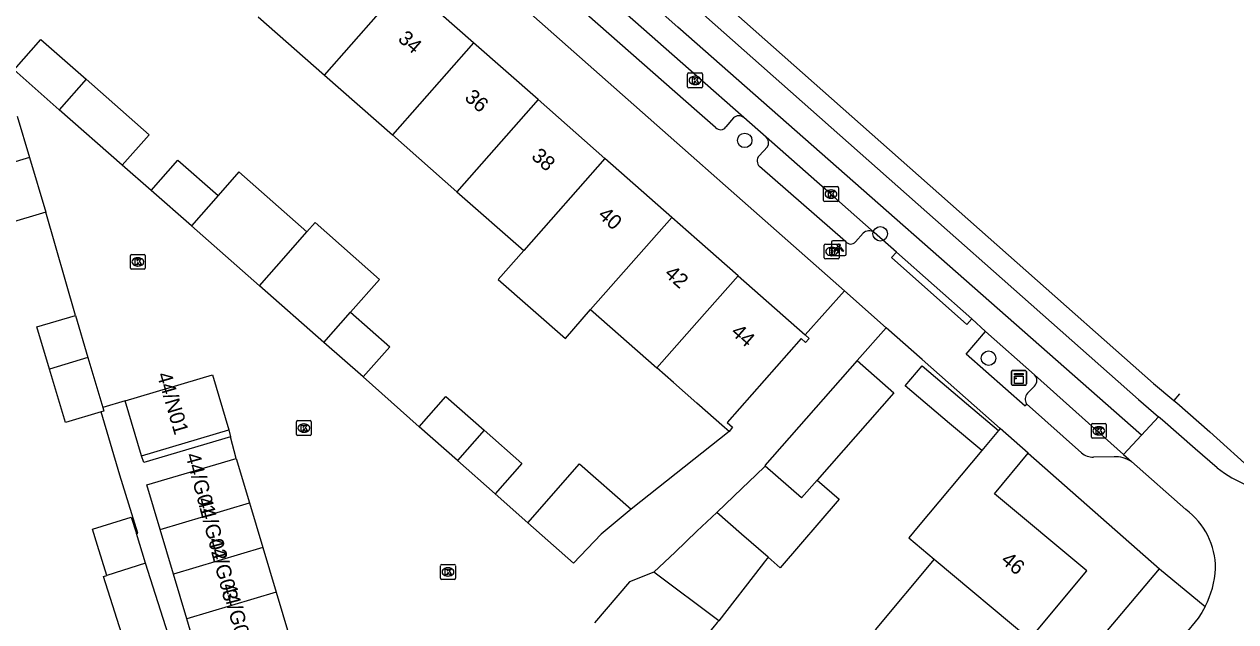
# Model space of a CAD drawing. Extents: x 162532 to 163264, y 381233 to 382042.
# Drawn here: x 162954.6 to 163036.3, y 381826.4 to 381866.7 of the extents above; entities that cross this region are included whole.
import ezdxf

# ---------------------------------------------------------------- set-up
doc = ezdxf.new("R2010")
doc.units = 0
for name, color, linetype in [('IMGEO_Boom', 7, 'Continuous'), ('IMGEO_Brandkraan', 7, 'Continuous'), ('IMGEO_Kast', 7, 'Continuous'), ('IMGEO_Kolk', 7, 'Continuous'), ('IMGEO_Lichtpunt', 7, 'Continuous'), ('IMGEO_Muur', 7, 'Continuous'), ('IMGEO_Pand', 7, 'Continuous'), ('IMGEO_Pand_nummerreeks', 7, 'Continuous'), ('IMGEO_Parkeervlak_open', 7, 'Continuous'), ('IMGEO_Rijbaan_lokaal_gesloten', 7, 'Continuous'), ('IMGEO_Rijbaan_lokaal_open', 7, 'Continuous'), ('IMGEO_Voetpad_open', 7, 'Continuous')]:
    doc.layers.add(name, color=color, linetype=linetype)

msp = doc.modelspace()

# ---------------------------------------------------------------- linework, layer by layer
at = {"layer": 'IMGEO_Boom'}
for centre in [(163003.224, 381858.903), (163012.36, 381852.6), (163019.663, 381844.21)]:
    msp.add_circle(centre, 0.489, dxfattribs=at)
at = {"layer": 'IMGEO_Brandkraan'}
for p, q in [((163008.59, 381850.977), (163008.59, 381851.829)), ((163008.665, 381851.903), (163009.517, 381851.903)), ((163009.078, 381851.683), (163009.103, 381851.683)), ((163009.591, 381851.829), (163009.591, 381850.977)), ((163009.517, 381850.903), (163008.665, 381850.903)), ((163009.101, 381851.123), (163009.076, 381851.123))]:
    msp.add_line(p, q, dxfattribs=at)
for points in [[(163008.59, 381850.977), (163008.59, 381851.829)], [(163008.665, 381851.903), (163009.517, 381851.903)], [(163008.938, 381851.603), (163008.938, 381851.203), (163009.151, 381851.203)], [(163009.169, 381851.603), (163008.938, 381851.603)], [(163009.117, 381851.522), (163009.063, 381851.522), (163009.063, 381851.446)], [(163009.063, 381851.446), (163009.116, 381851.446)], [(163009.591, 381851.829), (163009.591, 381850.977)], [(163009.517, 381850.903), (163008.665, 381850.903)], [(163009.125, 381851.37), (163009.063, 381851.37), (163009.063, 381851.289)], [(163009.063, 381851.289), (163009.125, 381851.289)]]:
    msp.add_lwpolyline(points, dxfattribs=at)
for centre, radius, start, end in [((163008.667, 381851.827), 0.0765, 91.55205, 178.44795), ((163008.667, 381851.827), 0.0765, 91.55205, 178.44795), ((163009.118, 381851.484), 0.0379, 267.82845, 90.93552), ((163009.173, 381851.458), 0.145, 59.4692, 91.53667), ((163009.198, 381851.505), 0.0922, 285.51372, 58.15012), ((163009.515, 381851.827), 0.0765, 1.55205, 88.44795), ((163009.515, 381851.827), 0.0765, 1.55205, 88.44795), ((163008.667, 381850.979), 0.0765, 181.55205, 268.44795), ((163008.667, 381850.979), 0.0765, 181.55205, 268.44795), ((163009.126, 381851.329), 0.0404, 269.87594, 90.50774), ((163009.157, 381851.454), 0.251, 268.66757, 293.53466), ((163009.203, 381851.313), 0.105, 301.31148, 78.98903), ((163009.515, 381850.979), 0.0765, 271.55205, 358.44795), ((163009.515, 381850.979), 0.0765, 271.55205, 358.44795)]:
    msp.add_arc(centre, radius, start, end, dxfattribs=at)
for centre, major_axis, ratio, start_param, end_param in [((163009.077, 381851.403), (-0.387, 0.002), 0.722429, 4.712389, 7.853982), ((163009.102, 381851.403), (-0.39, 0.002), 0.717154, 1.570796, 4.712389)]:
    msp.add_ellipse(centre, major_axis=major_axis, ratio=ratio, start_param=start_param, end_param=end_param, dxfattribs=at)
at = {"layer": 'IMGEO_Kast'}
for p, q in [((163021.212, 381842.46), (163021.212, 381843.301)), ((163021.212, 381843.301), (163021.212, 381842.46)), ((163021.287, 381843.385), (163022.128, 381843.385)), ((163022.128, 381843.385), (163021.287, 381843.385)), ((163022.212, 381843.31), (163022.212, 381842.469)), ((163022.212, 381842.469), (163022.212, 381843.31)), ((163022.137, 381842.385), (163021.296, 381842.385)), ((163021.296, 381842.385), (163022.137, 381842.385))]:
    msp.add_line(p, q, dxfattribs=at)
for points in [[(163021.407, 381843.175), (163022.007, 381843.175), (163022.007, 381843.09), (163021.407, 381843.09), (163021.407, 381843.175)], [(163021.407, 381843), (163022.007, 381843), (163022.007, 381842.511), (163021.407, 381842.511), (163021.407, 381843)]]:
    msp.add_lwpolyline(points, dxfattribs=at)
msp.add_circle((163021.491, 381842.849), 0.0377, dxfattribs=at)
for centre, start, end in [((163021.29, 381843.307), 92.4484, 184.28452), ((163021.29, 381843.307), 92.4484, 184.28452), ((163022.134, 381843.307), 2.4484, 94.28452), ((163022.134, 381843.307), 2.4484, 94.28452), ((163021.29, 381842.463), 182.4484, 274.28452), ((163021.29, 381842.463), 182.4484, 274.28452), ((163022.134, 381842.463), 272.4484, 4.28452), ((163022.134, 381842.463), 272.4484, 4.28452)]:
    msp.add_arc(centre, 0.0779, start, end, dxfattribs=at)
at = {"layer": 'IMGEO_Kolk'}
for p, q in [((162999.376, 381862.523), (162999.376, 381863.375)), ((162999.451, 381863.449), (163000.303, 381863.449)), ((162999.864, 381863.229), (162999.889, 381863.229)), ((163000.377, 381863.375), (163000.377, 381862.523)), ((163000.303, 381862.449), (162999.451, 381862.449)), ((162999.887, 381862.669), (162999.862, 381862.669)), ((163008.542, 381854.856), (163008.542, 381855.708)), ((163008.617, 381855.782), (163009.469, 381855.782)), ((163009.03, 381855.562), (163009.055, 381855.562)), ((163009.543, 381855.708), (163009.543, 381854.856)), ((163009.469, 381854.782), (163008.617, 381854.782)), ((163009.053, 381855.002), (163009.028, 381855.002)), ((162961.809, 381850.279), (162961.809, 381851.131)), ((162961.884, 381851.205), (162962.736, 381851.205)), ((162962.297, 381850.985), (162962.322, 381850.985)), ((162962.81, 381851.131), (162962.81, 381850.279)), ((162962.736, 381850.205), (162961.884, 381850.205)), ((162962.32, 381850.425), (162962.295, 381850.425)), ((162973.004, 381839.07), (162973.004, 381839.922)), ((162973.079, 381839.996), (162973.931, 381839.996)), ((162973.515, 381839.216), (162973.49, 381839.216)), ((162973.492, 381839.776), (162973.517, 381839.776)), ((162974.005, 381839.922), (162974.005, 381839.07)), ((163026.594, 381838.883), (163026.594, 381839.735)), ((163026.669, 381839.809), (163027.521, 381839.809)), ((163027.082, 381839.589), (163027.107, 381839.589)), ((163027.595, 381839.735), (163027.595, 381838.883)), ((162973.931, 381838.996), (162973.079, 381838.996)), ((163027.521, 381838.809), (163026.669, 381838.809)), ((163027.105, 381839.029), (163027.08, 381839.029)), ((162982.717, 381829.362), (162982.717, 381830.214)), ((162982.792, 381830.288), (162983.644, 381830.288)), ((162983.718, 381830.214), (162983.718, 381829.362)), ((162983.228, 381829.508), (162983.203, 381829.508)), ((162983.205, 381830.068), (162983.23, 381830.068)), ((162983.644, 381829.288), (162982.792, 381829.288))]:
    msp.add_line(p, q, dxfattribs=at)
for points in [[(162999.376, 381862.523), (162999.376, 381863.375)], [(162999.451, 381863.449), (163000.303, 381863.449)], [(162999.697, 381863.149), (162999.82, 381863.149), (162999.82, 381862.998), (162999.95, 381863.149), (163000.114, 381863.149), (162999.968, 381862.998), (163000.121, 381862.749), (162999.969, 381862.749), (162999.884, 381862.913), (162999.82, 381862.846), (162999.82, 381862.749), (162999.697, 381862.749), (162999.697, 381863.149)], [(163000.377, 381863.375), (163000.377, 381862.523)], [(163000.303, 381862.449), (162999.451, 381862.449)], [(163008.542, 381854.856), (163008.542, 381855.708)], [(163008.617, 381855.782), (163009.469, 381855.782)], [(163009.543, 381855.708), (163009.543, 381854.856)], [(163009.469, 381854.782), (163008.617, 381854.782)], [(163008.863, 381855.482), (163008.986, 381855.482), (163008.986, 381855.331), (163009.116, 381855.482), (163009.28, 381855.482), (163009.134, 381855.331), (163009.287, 381855.082), (163009.135, 381855.082), (163009.05, 381855.246), (163008.986, 381855.179), (163008.986, 381855.082), (163008.863, 381855.082), (163008.863, 381855.482)], [(162961.809, 381850.279), (162961.809, 381851.131)], [(162961.884, 381851.205), (162962.736, 381851.205)], [(162962.13, 381850.905), (162962.253, 381850.905), (162962.253, 381850.754), (162962.383, 381850.905), (162962.547, 381850.905), (162962.401, 381850.754), (162962.554, 381850.505), (162962.402, 381850.505), (162962.317, 381850.669), (162962.253, 381850.602), (162962.253, 381850.505), (162962.13, 381850.505), (162962.13, 381850.905)], [(162962.81, 381851.131), (162962.81, 381850.279)], [(162962.736, 381850.205), (162961.884, 381850.205)], [(162973.004, 381839.07), (162973.004, 381839.922)], [(162973.079, 381839.996), (162973.931, 381839.996)], [(162973.325, 381839.696), (162973.448, 381839.696), (162973.448, 381839.545), (162973.578, 381839.696), (162973.742, 381839.696), (162973.596, 381839.545), (162973.749, 381839.296), (162973.597, 381839.296), (162973.512, 381839.46), (162973.448, 381839.393), (162973.448, 381839.296), (162973.325, 381839.296), (162973.325, 381839.696)], [(162974.005, 381839.922), (162974.005, 381839.07)], [(163026.594, 381838.883), (163026.594, 381839.735)], [(163026.669, 381839.809), (163027.521, 381839.809)], [(163026.915, 381839.509), (163027.038, 381839.509), (163027.038, 381839.358), (163027.168, 381839.509), (163027.332, 381839.509), (163027.186, 381839.358), (163027.339, 381839.109), (163027.187, 381839.109), (163027.102, 381839.273), (163027.038, 381839.206), (163027.038, 381839.109), (163026.915, 381839.109), (163026.915, 381839.509)], [(163027.595, 381839.735), (163027.595, 381838.883)], [(162973.931, 381838.996), (162973.079, 381838.996)], [(163027.521, 381838.809), (163026.669, 381838.809)], [(162982.717, 381829.362), (162982.717, 381830.214)], [(162982.792, 381830.288), (162983.644, 381830.288)], [(162983.718, 381830.214), (162983.718, 381829.362)], [(162983.038, 381829.988), (162983.161, 381829.988), (162983.161, 381829.837), (162983.291, 381829.988), (162983.455, 381829.988), (162983.309, 381829.837), (162983.462, 381829.588), (162983.31, 381829.588), (162983.225, 381829.752), (162983.161, 381829.685), (162983.161, 381829.588), (162983.038, 381829.588), (162983.038, 381829.988)], [(162983.644, 381829.288), (162982.792, 381829.288)]]:
    msp.add_lwpolyline(points, dxfattribs=at)
for centre, start, end in [((162999.453, 381863.373), 91.55205, 178.44795), ((162999.453, 381863.373), 91.55205, 178.44795), ((163000.301, 381863.373), 1.55205, 88.44795), ((163000.301, 381863.373), 1.55205, 88.44795), ((162999.453, 381862.525), 181.55205, 268.44795), ((162999.453, 381862.525), 181.55205, 268.44795), ((163000.301, 381862.525), 271.55205, 358.44795), ((163000.301, 381862.525), 271.55205, 358.44795), ((163008.619, 381855.706), 91.55205, 178.44795), ((163008.619, 381855.706), 91.55205, 178.44795), ((163009.467, 381855.706), 1.55205, 88.44795), ((163009.467, 381855.706), 1.55205, 88.44795), ((163008.619, 381854.858), 181.55205, 268.44795), ((163008.619, 381854.858), 181.55205, 268.44795), ((163009.467, 381854.858), 271.55205, 358.44795), ((163009.467, 381854.858), 271.55205, 358.44795), ((162961.886, 381851.129), 91.55205, 178.44795), ((162961.886, 381851.129), 91.55205, 178.44795), ((162962.734, 381851.129), 1.55205, 88.44795), ((162962.734, 381851.129), 1.55205, 88.44795), ((162961.886, 381850.281), 181.55205, 268.44795), ((162961.886, 381850.281), 181.55205, 268.44795), ((162962.734, 381850.281), 271.55205, 358.44795), ((162962.734, 381850.281), 271.55205, 358.44795), ((162973.081, 381839.92), 91.55205, 178.44795), ((162973.081, 381839.92), 91.55205, 178.44795), ((162973.929, 381839.92), 1.55205, 88.44795), ((162973.929, 381839.92), 1.55205, 88.44795), ((163026.671, 381839.733), 91.55205, 178.44795), ((163026.671, 381839.733), 91.55205, 178.44795), ((163027.519, 381839.733), 1.55205, 88.44795), ((163027.519, 381839.733), 1.55205, 88.44795), ((162973.081, 381839.072), 181.55205, 268.44795), ((162973.081, 381839.072), 181.55205, 268.44795), ((162973.929, 381839.072), 271.55205, 358.44795), ((162973.929, 381839.072), 271.55205, 358.44795), ((163026.671, 381838.885), 181.55205, 268.44795), ((163026.671, 381838.885), 181.55205, 268.44795), ((163027.519, 381838.885), 271.55205, 358.44795), ((163027.519, 381838.885), 271.55205, 358.44795), ((162982.794, 381830.212), 91.55205, 178.44795), ((162982.794, 381830.212), 91.55205, 178.44795), ((162983.642, 381830.212), 1.55205, 88.44795), ((162983.642, 381830.212), 1.55205, 88.44795), ((162982.794, 381829.364), 181.55205, 268.44795), ((162982.794, 381829.364), 181.55205, 268.44795), ((162983.642, 381829.364), 271.55205, 358.44795), ((162983.642, 381829.364), 271.55205, 358.44795)]:
    msp.add_arc(centre, 0.0765, start, end, dxfattribs=at)
for centre, major_axis, ratio, start_param, end_param in [((162999.863, 381862.949), (-0.387, 0.002), 0.722429, 4.712389, 7.853982), ((162999.888, 381862.949), (-0.39, 0.002), 0.717154, 1.570796, 4.712389), ((163009.029, 381855.282), (-0.387, 0.002), 0.722429, 4.712389, 7.853982), ((163009.054, 381855.282), (-0.39, 0.002), 0.717154, 1.570796, 4.712389), ((162962.296, 381850.705), (-0.387, 0.002), 0.722429, 4.712389, 7.853982), ((162962.321, 381850.705), (-0.39, 0.002), 0.717154, 1.570796, 4.712389), ((162973.491, 381839.496), (-0.387, 0.002), 0.722429, 4.712389, 7.853982), ((162973.516, 381839.496), (-0.39, 0.002), 0.717154, 1.570796, 4.712389), ((163027.081, 381839.309), (-0.387, 0.002), 0.722429, 4.712389, 7.853982), ((163027.106, 381839.309), (-0.39, 0.002), 0.717154, 1.570796, 4.712389), ((162983.204, 381829.788), (-0.387, 0.002), 0.722429, 4.712389, 7.853982), ((162983.229, 381829.788), (-0.39, 0.002), 0.717154, 1.570796, 4.712389)]:
    msp.add_ellipse(centre, major_axis=major_axis, ratio=ratio, start_param=start_param, end_param=end_param, dxfattribs=at)
at = {"layer": 'IMGEO_Lichtpunt'}
for p, q in [((163009.068, 381852.028), (163009.068, 381851.221)), ((163009.068, 381852.028), (163009.068, 381851.221)), ((163009.97, 381852.123), (163009.162, 381852.123)), ((163009.97, 381852.123), (163009.162, 381852.123)), ((163010.064, 381851.221), (163010.064, 381852.028)), ((163010.064, 381851.221), (163010.064, 381852.028)), ((163009.162, 381851.127), (163009.97, 381851.127)), ((163009.162, 381851.127), (163009.97, 381851.127))]:
    msp.add_line(p, q, dxfattribs=at)
for points in [[(163009.442, 381851.692), (163009.481, 381851.664), (163009.293, 381851.402), (163009.255, 381851.429), (163009.442, 381851.692)], [(163009.544, 381851.644), (163009.591, 381851.644), (163009.591, 381851.322), (163009.544, 381851.322), (163009.544, 381851.644)], [(163009.654, 381851.664), (163009.692, 381851.691), (163009.879, 381851.429), (163009.84, 381851.401), (163009.654, 381851.664)]]:
    msp.add_lwpolyline(points, dxfattribs=at)
msp.add_circle((163009.567, 381851.826), 0.0994, dxfattribs=at)
for centre, start, end in [((163009.162, 381852.028), 90, 180), ((163009.162, 381852.028), 90, 180), ((163009.97, 381852.028), 0, 90), ((163009.97, 381852.028), 0, 90), ((163009.162, 381851.221), 180, 270), ((163009.162, 381851.221), 180, 270), ((163009.97, 381851.221), 270, 0), ((163009.97, 381851.221), 270, 360)]:
    msp.add_arc(centre, 0.0946, start, end, dxfattribs=at)
at = {"layer": 'IMGEO_Muur'}
msp.add_lwpolyline([(163002.168, 381839.272), (162995.563, 381834.021)], dxfattribs=at)
at = {"layer": 'IMGEO_Pand'}
for points in [[(162974.886, 381863.312), (162980.362, 381869.524)], [(162984.945, 381865.485), (162980.362, 381869.524)], [(162970.419, 381867.248), (162974.886, 381863.312)], [(162953.965, 381863.657), (162955.774, 381865.71), (162958.82, 381863.026)], [(162984.945, 381865.485), (162979.47, 381859.272)], [(162989.296, 381861.65), (162984.945, 381865.485)], [(162957.011, 381860.973), (162953.965, 381863.657)], [(162958.82, 381863.026), (162957.011, 381860.973)], [(162958.82, 381863.026), (162963.063, 381859.288), (162961.254, 381857.235)], [(162974.886, 381863.312), (162979.47, 381859.272)], [(162989.296, 381861.65), (162983.821, 381855.439)], [(162993.798, 381857.682), (162989.296, 381861.65)], [(162954.166, 381860.543), (162954.996, 381857.752)], [(162961.254, 381857.235), (162957.011, 381860.973)], [(162979.47, 381859.272), (162983.821, 381855.439)], [(162954.996, 381857.752), (162952.367, 381856.971)], [(162954.996, 381857.752), (162956.096, 381854.056)], [(162963.216, 381855.522), (162965.015, 381857.564), (162967.719, 381855.182)], [(162993.798, 381857.682), (162988.324, 381851.471)], [(162998.309, 381853.707), (162993.798, 381857.682)], [(162956.096, 381854.056), (162953.466, 381853.274), (162952.367, 381856.971)], [(162973.712, 381852.737), (162969.126, 381856.778), (162967.719, 381855.182)], [(162965.919, 381853.14), (162963.216, 381855.522)], [(162967.719, 381855.182), (162965.919, 381853.14)], [(162983.821, 381855.439), (162988.324, 381851.471)], [(162970.505, 381849.099), (162965.919, 381853.14)], [(162976.655, 381847.309), (162978.605, 381849.522), (162974.256, 381853.355), (162973.712, 381852.737)], [(162992.834, 381847.497), (162998.309, 381853.707)], [(163002.779, 381849.766), (163000, 381852.216), (162998.309, 381853.707)], [(162970.505, 381849.099), (162972.305, 381851.141), (162973.712, 381852.737)], [(162988.324, 381851.471), (162986.609, 381849.516), (162991.15, 381845.534), (162992.834, 381847.497)], [(162974.854, 381845.267), (162970.505, 381849.099)], [(162997.307, 381843.556), (163000, 381846.613), (163002.779, 381849.766)], [(163002.779, 381849.766), (163007.303, 381845.78)], [(162992.834, 381847.497), (162997.307, 381843.556)], [(162956.353, 381843.476), (162955.506, 381846.323), (162958.098, 381847.094)], [(162958.098, 381847.094), (162958.945, 381844.247)], [(162974.854, 381845.267), (162976.655, 381847.309)], [(162976.655, 381847.309), (162979.293, 381844.985), (162977.493, 381842.942)], [(163007.303, 381845.78), (163007.569, 381845.545), (163007.329, 381845.273), (163007.03, 381845.537), (163002.037, 381839.874), (163002.409, 381839.546), (163002.168, 381839.272)], [(162977.493, 381842.942), (162974.854, 381845.267)], [(162958.945, 381844.247), (162956.353, 381843.476)], [(162958.945, 381844.247), (162959.945, 381840.884)], [(162959.826, 381840.581), (162957.426, 381839.867), (162956.353, 381843.476)], [(163002.168, 381839.272), (163001.86, 381839.544), (163000, 381841.183), (162998.417, 381842.578), (162997.307, 381843.556)], [(163010.813, 381844.047), (163004.569, 381836.966), (163004.609, 381836.93)], [(163010.813, 381844.047), (163013.288, 381841.865), (163008.108, 381835.988)], [(163019.202, 381837.982), (163017.04, 381839.811), (163014.052, 381842.339), (163015.193, 381843.688), (163018.181, 381841.16), (163020.334, 381839.338)], [(162961.462, 381841.336), (162967.333, 381843.083), (162968.436, 381839.372)], [(162959.945, 381840.884), (162960.018, 381840.638), (162959.826, 381840.581)], [(162962.566, 381837.626), (162961.462, 381841.336)], [(162981.28, 381839.575), (162983.082, 381841.62), (162985.654, 381839.354)], [(162962.566, 381837.626), (162968.436, 381839.372)], [(162983.852, 381837.309), (162981.28, 381839.575)], [(162985.654, 381839.354), (162983.852, 381837.309)], [(162985.654, 381839.354), (162988.204, 381837.107), (162986.402, 381835.061)], [(163020.334, 381839.338), (163019.202, 381837.982)], [(163020.45, 381839.477), (163020.334, 381839.338)], [(163022.344, 381837.805), (163020.45, 381839.477)], [(163019.202, 381837.982), (163014.913, 381832.847), (163014.279, 381832.088), (163015.993, 381830.656)], [(163022.448, 381825.264), (163026.287, 381829.86), (163020.055, 381835.066), (163022.344, 381837.805)], [(162963.812, 381832.65), (162962.918, 381835.657), (162968.948, 381837.45)], [(162968.948, 381837.45), (162969.842, 381834.443)], [(162986.402, 381835.061), (162983.852, 381837.309)], [(162988.598, 381833.103), (162992.096, 381837.075), (162995.563, 381834.021)], [(163004.609, 381836.93), (163003.972, 381836.322), (163003.049, 381835.442), (163001.339, 381833.81)], [(163008.108, 381835.988), (163007.045, 381834.783), (163004.609, 381836.93)], [(163008.108, 381835.988), (163009.581, 381834.699), (163005.62, 381830.065), (163004.802, 381830.78)], [(162963.812, 381832.65), (162969.842, 381834.443)], [(162969.842, 381834.443), (162970.737, 381831.437)], [(162960.213, 381829.556), (162959.588, 381831.566), (162959.244, 381832.672), (162961.866, 381833.489), (162962.21, 381832.382)], [(162995.563, 381834.021), (162993.54, 381832.337), (162991.685, 381830.384), (162988.598, 381833.103)], [(163001.339, 381833.81), (163000, 381832.532), (162998.532, 381831.131), (162997.107, 381829.771)], [(163004.802, 381830.78), (163003.018, 381832.341), (163001.339, 381833.81)], [(162962.829, 381830.391), (162962.21, 381832.382)], [(162964.707, 381829.643), (162963.812, 381832.65)], [(162970.737, 381831.437), (162964.707, 381829.643)], [(162970.737, 381831.437), (162971.631, 381828.43)], [(162962.829, 381830.391), (162960.213, 381829.556)], [(162964.294, 381825.56), (162964.364, 381825.582), (162962.829, 381830.391)], [(163004.802, 381830.78), (163004.732, 381830.69), (163004.629, 381830.557), (163004.565, 381830.475), (163004.343, 381830.188), (163001.473, 381826.491)], [(163015.993, 381830.656), (163012.008, 381825.886)], [(163015.993, 381830.656), (163022.448, 381825.264)], [(162964.294, 381825.56), (162961.523, 381824.675), (162959.988, 381829.484), (162960.213, 381829.556)], [(162965.601, 381826.636), (162964.707, 381829.643)], [(162997.107, 381829.771), (162995.45, 381829.117), (162993.09, 381826.366)], [(163001.473, 381826.491), (162997.107, 381829.771)], [(162971.631, 381828.43), (162965.601, 381826.636)], [(162971.631, 381828.43), (162972.525, 381825.423)], [(162966.495, 381823.63), (162965.601, 381826.636)], [(163001.473, 381826.491), (163001.369, 381826.369), (163001.082, 381826.028), (162997.88, 381822.23), (162997.663, 381822.417)]]:
    msp.add_lwpolyline(points, dxfattribs=at)
at = {"layer": 'IMGEO_Parkeervlak_open'}
msp.add_lwpolyline([(163022.767, 381842.333), (163022.282, 381841.85)], dxfattribs=at)
for centre, radius, start, end in [((163022.38, 381842.712), 0.542, 315.56566, 44.58512), ((163022.775, 381841.449), 0.636, 140.85906, 210.8017)]:
    msp.add_arc(centre, radius, start, end, dxfattribs=at)
at = {"layer": 'IMGEO_Rijbaan_lokaal_gesloten'}
for points in [[(162960.555, 381904.688), (162964.495, 381901.237), (163030.789, 381842.506), (163032.151, 381841.367)], [(162959.588, 381903.618), (162963.496, 381900.145), (163029.773, 381841.426), (163031.123, 381840.264)], [(163029.975, 381839.023), (162998.723, 381866.534), (162984.668, 381879.012), (162958.336, 381902.201)], [(163003.157, 381860.44), (163000, 381863.226), (162991.553, 381870.7)], [(163004.675, 381859.124), (163003.157, 381860.44)], [(163011.941, 381852.697), (163009.04, 381855.284), (163004.675, 381859.124)], [(163013.455, 381851.365), (163011.941, 381852.697)], [(163013.455, 381851.365), (163018.527, 381846.856)], [(163019.464, 381846.01), (163018.527, 381846.856)], [(163019.464, 381846.01), (163022.766, 381843.093)], [(163028.767, 381837.716), (163022.766, 381843.093)]]:
    msp.add_lwpolyline(points, dxfattribs=at)
at = {"layer": 'IMGEO_Rijbaan_lokaal_open'}
for points in [[(162963.216, 381855.522), (162961.254, 381857.235)], [(162958.098, 381847.094), (162956.096, 381854.056)], [(163009.953, 381848.745), (163007.303, 381845.78)], [(163012.767, 381846.26), (163009.953, 381848.745)], [(163012.767, 381846.26), (163010.813, 381844.047)], [(162981.28, 381839.575), (162977.493, 381842.942)], [(163032.53, 381841.809), (163032.151, 381841.367)], [(162961.462, 381841.336), (162959.945, 381840.884)], [(163032.151, 381841.367), (163032.351, 381841.2), (163034.587, 381839.245), (163037.615, 381836.491)], [(163031.123, 381840.264), (163029.975, 381839.023)], [(163035.073, 381836.804), (163033.583, 381838.09), (163031.383, 381840.04), (163031.123, 381840.264)], [(162968.436, 381839.372), (162968.56, 381838.907)], [(163002.168, 381839.272), (162995.563, 381834.021)], [(162968.948, 381837.45), (162968.56, 381838.907)], [(163029.975, 381839.023), (163028.767, 381837.716)], [(163028.767, 381837.716), (163029.301, 381837.237)], [(163029.301, 381837.237), (163032.966, 381834.001)], [(162988.598, 381833.103), (162986.402, 381835.061)], [(163034.271, 381827.468), (163034.045, 381827.064), (163033.791, 381826.677), (163031.945, 381824.423)]]:
    msp.add_lwpolyline(points, dxfattribs=at)
for centre, radius, start, end in [((163040.223, 381843.505), 8.452, 232.45589, 248.77135), ((163029.978, 381829.999), 4.994, 0.19027, 53.24997), ((163028.493, 381830.428), 6.493, 332.8749, 356.36006)]:
    msp.add_arc(centre, radius, start, end, dxfattribs=at)
at = {"layer": 'IMGEO_Voetpad_open'}
for points in [[(162969.525, 381884.497), (163000, 381857.535), (163001.931, 381855.827), (163009.953, 381848.745)], [(163001.263, 381859.77), (163000, 381860.883), (162991.105, 381868.722)], [(163002.457, 381860.419), (163001.956, 381859.806)], [(163004.192, 381857.868), (163004.752, 381858.461)], [(163010.025, 381852.084), (163004.231, 381857.137)], [(163011.212, 381852.638), (163010.703, 381852.049)], [(163018.527, 381846.856), (163018.195, 381846.483), (163013.123, 381850.992), (163013.455, 381851.365)], [(163020.45, 381839.477), (163015.189, 381844.122), (163012.767, 381846.26)], [(163022.229, 381841.123), (163022.134, 381840.979), (163018.152, 381844.491), (163019.464, 381846.01)], [(163025.932, 381837.829), (163022.229, 381841.123)], [(162962.21, 381832.382), (162962.309, 381832.413), (162961.097, 381836.308), (162959.826, 381840.581)], [(162968.56, 381838.907), (162962.715, 381837.168), (162962.566, 381837.626)], [(163022.344, 381837.805), (163031.179, 381830.005)], [(163028.124, 381837.564), (163026.742, 381837.537)], [(162997.617, 381790.181), (162997.806, 381790.405), (163031.179, 381830.005)], [(163031.179, 381830.005), (163034.271, 381827.468)]]:
    msp.add_lwpolyline(points, dxfattribs=at)
for centre, radius, start, end in [((163002.819, 381860.041), 0.523, 49.67655, 133.76017), ((163001.595, 381860.067), 0.445, 221.77948, 324.16799), ((163004.286, 381858.743), 0.544, 328.8126, 44.43657), ((163004.58, 381857.522), 0.52, 138.28689, 227.82096), ((163011.612, 381852.228), 0.573, 54.95455, 134.2995), ((163010.379, 381852.35), 0.442, 216.93044, 317.15932), ((163026.723, 381838.753), 1.216, 229.43854, 270.91362), ((163028.181, 381835.488), 2.077, 57.3733, 91.57346)]:
    msp.add_arc(centre, radius, start, end, dxfattribs=at)

# ---------------------------------------------------------------- texts
at = {"layer": 'IMGEO_Pand_nummerreeks'}
for s, rotation, p in [('34', 318.60769, (162979.781, 381865.665)), ('36', 318.60769, (162984.278, 381861.701)), ('38', 318.60769, (162988.777, 381857.735)), ('40', 318.60769, (162993.274, 381853.772)), ('42', 318.60769, (162997.752, 381849.824)), ('44', 318.6084, (163002.236, 381845.873)), ('44/N01', 286.40403, (162963.585, 381843.11)), ('44/G01', 284.84762, (162965.513, 381837.686)), ('44/G02', 284.84762, (162966.306, 381834.695)), ('44/G03', 284.84762, (162967.026, 381831.975)), ('46', 320.12787, (163020.434, 381830.475)), ('44/G04', 284.84762, (162967.948, 381828.891))]:
    msp.add_text(s, height=1, rotation=rotation, dxfattribs=at).set_placement(p)

doc.saveas('drawing.dxf')
